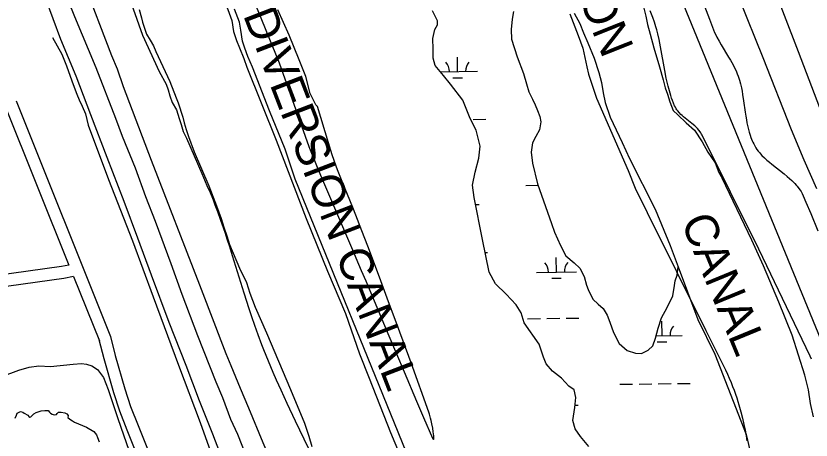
# Model space of a CAD drawing. Extents: x 3715084 to 3753216, y 488173 to 513963.
# Drawn here: x 3731481 to 3733466, y 495879 to 496938 of the extents above; entities that cross this region are included whole.
import ezdxf

# ---------------------------------------------------------------- set-up
doc = ezdxf.new("R2010")
doc.units = 0
for name, color, linetype in [('V-LEVE-TOET', 7, 'Continuous'), ('V-RIVR-IDEN', 7, 'Continuous'), ('V-ROAD-CNTR', 7, 'Continuous'), ('V-SITE-OTLN', 7, 'Continuous'), ('V-SITE-VEGE', 7, 'Continuous'), ('V-TOPO-BNDY', 7, 'Continuous'), ('V-TOPO-SHOR', 7, 'Continuous'), ('V-WETL-SWMP', 7, 'Continuous')]:
    doc.layers.add(name, color=color, linetype=linetype)

msp = doc.modelspace()

# ---------------------------------------------------------------- linework, layer by layer
at = {"layer": 'V-LEVE-TOET'}
for points in [[(3733487.1, 496708.6), (3733434.3, 496848.6), (3733368.3, 497020.1)], [(3731597.9, 497011.3), (3731627.9, 496936.7)], [(3731593.5, 496878.9), (3731555.3, 496983.4)], [(3733286.3, 496981.5), (3733345.1, 496834.6), (3733415.8, 496654.4), (3733447.8, 496578.7), (3733479.4, 496506.9)], [(3731627.9, 496936.7), (3731681.1, 496809.1), (3731730.1, 496682.5), (3731746.7, 496638.2), (3731779.1, 496558.5), (3731804.9, 496487.1), (3731829, 496426.1), (3731868.3, 496319.9), (3731895.6, 496243.2), (3731934.4, 496140.2), (3731980.4, 496025.1), (3731996.7, 495985.4), (3732017.1, 495931.6), (3732034.5, 495893.8), (3732054.2, 495843.7)], [(3731751.6, 496475.2), (3731709.1, 496584.4), (3731668.5, 496691.3), (3731631.8, 496787.7), (3731593.5, 496878.9)], [(3732001, 495819.8), (3731973, 495894.5), (3731939.7, 495977.5), (3731906.1, 496065.7), (3731864.2, 496173), (3731820.2, 496291), (3731785.8, 496383.7), (3731751.6, 496475.2)]]:
    msp.add_lwpolyline(points, dxfattribs=at)
at = {"layer": 'V-ROAD-CNTR'}
for points in [[(3731481.9, 496725.7), (3731717.5, 496138)], [(3731454, 496714.5), (3731613.7, 496316.3)], [(3731613.7, 496316.3), (3731595.5, 496312.3), (3730222.2, 496120.5)], [(3731625, 496288), (3731600.8, 496282.7), (3730229, 496091.2)], [(3731625, 496288), (3731689.7, 496126.8)], [(3731688.6, 496130.7), (3731700.5, 496082.9), (3731724.7, 495998.1), (3731739.6, 495952.8), (3731758.5, 495905.1), (3731822.4, 495744.3), (3731856.9, 495661.6), (3731870.5, 495631.4), (3731886.5, 495592.8), (3731907, 495536), (3731942.4, 495444.7), (3731995.8, 495300.1), (3732029.3, 495210.1), (3732064.1, 495118.1), (3732093.3, 495044.3), (3732122.5, 494975.3), (3732151.9, 494910.5)], [(3731717.7, 496138), (3731729.4, 496090.6), (3731753.3, 496006.9), (3731767.8, 495963.1), (3731786.4, 495916.1), (3731850.2, 495755.6), (3731884.4, 495673.6), (3731898.1, 495643.3), (3731914.4, 495603.6), (3731935.1, 495546.6), (3731970.5, 495455.3), (3732023.9, 495310.5), (3732057.4, 495220.7), (3732092.1, 495128.9), (3732121, 495055.7), (3732150, 494987.4), (3732179.2, 494923), (3732205.9, 494864.4)]]:
    msp.add_lwpolyline(points, dxfattribs=at)
at = {"layer": 'V-SITE-OTLN'}
for p, q in [((3731567.5, 496062.8), (3731624.1, 496069.1)), ((3731624.1, 496069.1), (3731645.2, 496070.7)), ((3731645.2, 496070.7), (3731657.4, 496069.1)), ((3731657.4, 496069.1), (3731671, 496064.7)), ((3731446, 496037.9), (3731488.5, 496054.2)), ((3731488.5, 496054.2), (3731514.2, 496061.1)), ((3731514.2, 496061.1), (3731538.3, 496064.8)), ((3731538.3, 496064.8), (3731567.5, 496062.8)), ((3731671, 496064.7), (3731685.1, 496055.6)), ((3731685.1, 496055.6), (3731700.3, 496035.5)), ((3731700.3, 496035.5), (3731711.9, 496005.3)), ((3731711.9, 496005.3), (3731735.5, 495933.3)), ((3731735.5, 495933.3), (3731778.5, 495809.9))]:
    msp.add_line(p, q, dxfattribs=at)
at = {"layer": 'V-SITE-VEGE'}
for p, q in [((3732069, 496991.8), (3732103.1, 496906.4)), ((3732039.3, 496922.2), (3732027.3, 496955.1)), ((3732163.1, 496889.9), (3732135.4, 496953.2)), ((3732863.5, 496942.8), (3732884.4, 496889)), ((3732043.1, 496902.6), (3732039.3, 496922.2)), ((3732046.8, 496874.8), (3732043.1, 496902.6)), ((3732103.1, 496906.4), (3732138.5, 496821.1)), ((3732188.4, 496828), (3732163.1, 496889.9)), ((3732884.4, 496889), (3732895.8, 496857.4)), ((3732052.5, 496857.1), (3732046.8, 496874.8)), ((3732060.1, 496836.3), (3732052.5, 496857.1)), ((3732895.8, 496857.4), (3732905.8, 496810.7)), ((3732071.5, 496809.7), (3732060.1, 496836.3)), ((3732138.5, 496821.1), (3732212, 496611.9)), ((3732205.2, 496786.9), (3732188.4, 496828)), ((3732114.6, 496700.9), (3732071.5, 496809.7)), ((3732905.8, 496810.7), (3732910.2, 496792.3)), ((3732215.8, 496744), (3732205.2, 496786.9)), ((3732910.2, 496792.3), (3732930.6, 496732.8)), ((3732230.1, 496715.9), (3732215.8, 496744)), ((3732930.6, 496732.8), (3733009.5, 496552)), ((3732233.9, 496711.5), (3732230.1, 496715.9)), ((3732261.6, 496621.6), (3732233.9, 496711.5)), ((3732153.2, 496605.1), (3732114.6, 496700.9)), ((3732166, 496567.6), (3732153.2, 496605.1)), ((3732212, 496611.9), (3732231.3, 496564.7)), ((3732270.8, 496591.6), (3732261.6, 496621.6)), ((3732275.4, 496577.4), (3732270.8, 496591.6)), ((3732178.5, 496530.7), (3732166, 496567.6)), ((3732231.3, 496564.7), (3732245.4, 496530.9)), ((3732280.3, 496563.3), (3732275.4, 496577.4)), ((3732283.8, 496553.9), (3732280.3, 496563.3)), ((3732288.6, 496541.5), (3732283.8, 496553.9)), ((3733009.5, 496552), (3733026.9, 496508.3)), ((3732455, 495850.5), (3732178.5, 496530.7)), ((3732245.4, 496530.9), (3732246.2, 496529.1)), ((3732246.2, 496529.1), (3732318.9, 496359.9)), ((3732295.2, 496525.1), (3732288.6, 496541.5)), ((3732322.5, 496459.5), (3732295.2, 496525.1)), ((3733026.9, 496508.3), (3733056.8, 496447.3)), ((3732330, 496440.7), (3732322.5, 496459.5)), ((3733056.8, 496447.3), (3733203, 496152.8)), ((3732344.9, 496402), (3732330, 496440.7)), ((3732359.7, 496363.2), (3732344.9, 496402)), ((3732318.9, 496359.9), (3732343.4, 496302.9)), ((3732388.9, 496285.6), (3732359.7, 496363.2)), ((3732343.4, 496302.9), (3732354.6, 496276.7)), ((3732408.2, 496233.7), (3732388.9, 496285.6)), ((3732354.6, 496276.7), (3732375.6, 496227.1)), ((3732375.6, 496227.1), (3732412.4, 496139.8)), ((3732433.7, 496164.5), (3732408.2, 496233.7)), ((3732467.5, 496072.2), (3732433.7, 496164.5)), ((3733203, 496152.8), (3733251.8, 496054.6)), ((3732412.4, 496139.8), (3732450.1, 496050)), ((3732512.2, 495949.2), (3732467.5, 496072.2)), ((3732450.1, 496050), (3732481.4, 495976.2)), ((3733251.8, 496054.6), (3733256.9, 496044)), ((3733256.9, 496044), (3733261.6, 496033.6)), ((3733261.6, 496033.6), (3733265.9, 496023.4)), ((3733265.9, 496023.4), (3733269.9, 496013.4)), ((3733269.9, 496013.4), (3733273.5, 496003.7)), ((3733273.5, 496003.7), (3733276.9, 495994.2)), ((3733276.9, 495994.2), (3733280, 495984.9)), ((3732481.4, 495976.2), (3732498.9, 495935.6)), ((3733280, 495984.9), (3733282.8, 495975.9)), ((3733282.8, 495975.9), (3733285.5, 495967.1)), ((3732513.9, 495943.8), (3732512.2, 495949.2)), ((3733285.5, 495967.1), (3733290.2, 495950)), ((3733290.2, 495950), (3733294.3, 495933.8)), ((3732498.9, 495935.6), (3732521.2, 495884.6)), ((3732516.4, 495934.5), (3732513.9, 495943.8)), ((3732517.8, 495928.5), (3732516.4, 495934.5)), ((3732519.5, 495920.1), (3732517.8, 495928.5)), ((3733294.3, 495933.8), (3733297.8, 495918.5)), ((3732521.5, 495908.9), (3732519.5, 495920.1)), ((3732523, 495899.6), (3732521.5, 495908.9)), ((3733297.8, 495918.5), (3733300.8, 495904)), ((3732524.1, 495890.3), (3732523, 495899.6)), ((3732524.3, 495886.1), (3732524.1, 495890.3)), ((3733300.8, 495904), (3733303.4, 495890.4)), ((3733303.4, 495890.4), (3733305.7, 495877.6)), ((3732521.2, 495884.6), (3732522.5, 495882)), ((3732522.5, 495882), (3732523, 495881.4)), ((3732523, 495881.4), (3732523.4, 495881.2)), ((3732523.4, 495881.2), (3732523.7, 495881.2)), ((3732523.7, 495881.2), (3732524, 495881.6)), ((3732524, 495881.6), (3732524.2, 495882.1)), ((3732524.2, 495882.1), (3732524.3, 495883.8)), ((3732524.3, 495883.8), (3732524.3, 495886.1))]:
    msp.add_line(p, q, dxfattribs=at)
for points in [[(3731703.4, 497156.2), (3731797.2, 496889.8), (3731838.8, 496799.1), (3731856.5, 496767.7), (3731861.2, 496753.6), (3731865.5, 496738.2), (3731871.1, 496722.1), (3731882, 496703.3), (3731888.9, 496681.8), (3731893.9, 496667.1), (3731898.9, 496649.7), (3731907, 496633.2), (3731945.5, 496544.6), (3731958.3, 496515), (3731966, 496496.9), (3731973.4, 496478.6), (3731978.2, 496466.4), (3731984.3, 496450), (3731992.3, 496428), (3732002.5, 496398.5), (3732008.1, 496381.6), (3732014.4, 496362.2), (3732021.5, 496340), (3732050.5, 496246.8), (3732062.9, 496208.2), (3732069.7, 496187.6), (3732077.1, 496165.8), (3732085.4, 496142.7), (3732094.5, 496118.1), (3732099.4, 496105.5), (3732111, 496077), (3732122.9, 496048.6), (3732131.1, 496029.8), (3732142.3, 496004.8), (3732157.5, 495971.6), (3732178.3, 495927.5), (3732244.2, 495790.9)], [(3732317.8, 495345.7), (3732291.4, 495411.2), (3732255.8, 495498.3), (3732208.1, 495614.3), (3732181.2, 495679), (3732153.9, 495743.7), (3732098.8, 495872.8), (3732062.4, 495958.9), (3732041.8, 496008.3), (3732018.6, 496064.8), (3732006.5, 496095), (3731993.6, 496127.3), (3731980.2, 496161.9), (3731940.2, 496265.8), (3731820.1, 496577.5), (3731750.2, 496760.6), (3731735.2, 496804.9), (3731721.1, 496838.6), (3731649.9, 497024)], [(3733181.2, 497010.9), (3733211.8, 496929.9), (3733222.2, 496903.1), (3733224.9, 496896.5), (3733227.7, 496890.5), (3733230.4, 496884.9), (3733235.9, 496874.6), (3733241, 496865.7)], [(3733466.3, 496081.3), (3733463.1, 496088.5), (3733335.3, 496355.8), (3733193.9, 496640.5), (3733192.4, 496643.2), (3733190.8, 496645.8), (3733189.2, 496648.3), (3733185.8, 496652.7), (3733182.2, 496656.7), (3733178.7, 496660.3), (3733175.2, 496663.6), (3733168.3, 496669.5), (3733151.2, 496683.2), (3733147.2, 496686.5), (3733143.8, 496689.5), (3733141, 496692.2), (3733136.3, 496697.1), (3733133, 496701), (3733130.8, 496704), (3733129.2, 496706.4), (3733127.1, 496710), (3733125.2, 496713.9), (3733122.5, 496720.4), (3733120, 496726.8), (3733117.7, 496733.1), (3733115.6, 496739.1), (3733112, 496751), (3733108.9, 496762.3), (3733106.3, 496773), (3733104.1, 496783), (3733100.3, 496802), (3733089.9, 496860.5), (3733086.2, 496879.2), (3733083, 496893), (3733080.4, 496903.3), (3733078.3, 496911), (3733074.7, 496922.4), (3733070.8, 496933.7), (3733064.3, 496950.5)], [(3733241, 496865.7), (3733259.7, 496835.1), (3733264.3, 496827.4), (3733270.9, 496815.7), (3733274.1, 496809.8), (3733277, 496803.9), (3733279.5, 496798.5), (3733281.6, 496793.2), (3733283.6, 496788), (3733285.3, 496782.9), (3733286.9, 496778), (3733289.5, 496768.2), (3733291.7, 496758.9), (3733293.4, 496750), (3733294.9, 496741.7), (3733297.3, 496725.9), (3733301.2, 496698.1), (3733302.8, 496687.7), (3733304.3, 496678.7), (3733305.7, 496670.9), (3733307.1, 496664.1), (3733308.5, 496658.2), (3733311.2, 496647.9), (3733313.5, 496640.4), (3733315.4, 496634.8), (3733318.7, 496626.6), (3733320.5, 496622.6), (3733322.4, 496618.6), (3733325, 496613.7), (3733327.7, 496609.1), (3733330.6, 496604.8), (3733333.6, 496600.8), (3733336.7, 496597), (3733339.8, 496593.4), (3733342.9, 496590), (3733349.3, 496583.7), (3733355.6, 496577.9), (3733361.8, 496572.7), (3733367.6, 496567.9), (3733398.8, 496543.6), (3733406.1, 496537.6), (3733412.2, 496532.3), (3733417.4, 496527.5), (3733421.8, 496523.3), (3733425.4, 496519.4), (3733428.5, 496515.9), (3733431.1, 496512.9), (3733435.4, 496507.3), (3733438.4, 496502.9), (3733440.5, 496499.6), (3733443.4, 496494.4), (3733445.9, 496489), (3733452.9, 496472.9), (3733464.8, 496444.6), (3733482.5, 496402)]]:
    msp.add_lwpolyline(points, dxfattribs=at)
at = {"layer": 'V-TOPO-BNDY'}
msp.add_lwpolyline([(3732402.5, 498784.6), (3732445.6, 498679.6), (3734453, 493779.6)], dxfattribs=at)
at = {"layer": 'V-TOPO-SHOR'}
for points in [[(3732001, 496979.4), (3732020, 496926.3), (3732024.4, 496899.2), (3732032, 496876.4), (3732039.5, 496858.1), (3732050.3, 496832.1), (3732057.9, 496810)], [(3733046.3, 496964.2), (3733053.3, 496937), (3733057.7, 496916.8), (3733064, 496892.8), (3733073.5, 496858.7), (3733087.4, 496811.2), (3733096.2, 496778.4), (3733101.9, 496758.1), (3733107.6, 496742.3), (3733113.3, 496723.4), (3733121.5, 496701.9), (3733132.8, 496691.1), (3733154.3, 496671.5), (3733174.6, 496652.5), (3733193.5, 496624.1), (3733208, 496598.2), (3733226.4, 496571.6), (3733235.8, 496547.6), (3733244, 496533.1)], [(3731789.3, 496953.6), (3731795, 496933.4), (3731797.5, 496922), (3731807.6, 496892.3), (3731816.4, 496877.1), (3731824.6, 496863.2), (3731831, 496849.3), (3731836.6, 496836.7)], [(3732874.4, 496944.7), (3732888.9, 496919.4), (3732897.8, 496895.4), (3732908.5, 496870.7), (3732924.3, 496832.8), (3732936.3, 496796.8), (3732942.6, 496772.1), (3732947, 496746.2), (3732952.1, 496721.5), (3732964.1, 496685.5), (3732994.4, 496621.7), (3733012.7, 496581.8)], [(3731573.2, 496884.2), (3731596.5, 496842.2), (3731607.7, 496813.4), (3731616.9, 496787.4), (3731624.5, 496766.7), (3731633.7, 496742.3), (3731639.3, 496728.7), (3731646.6, 496712.9), (3731654.8, 496693.8), (3731661.8, 496665.3)], [(3731836.6, 496836.7), (3731865.9, 496774.2), (3731881.6, 496733.2), (3731886.7, 496721.2), (3731897.9, 496685), (3731901.6, 496670.9), (3731906.6, 496654.9), (3731912.2, 496636.8), (3731926.7, 496598.6), (3731962.8, 496514), (3731982.3, 496463.7), (3731993.6, 496432.8), (3732000.5, 496410.7), (3732008, 496389.3), (3732014.8, 496367.2), (3732039.5, 496308.8), (3732056.7, 496272.5), (3732065.4, 496246.3), (3732078.7, 496210.8), (3732106.6, 496147), (3732166.7, 496006), (3732201.5, 495921.4), (3732212.1, 495889.3), (3732219.5, 495863.8)], [(3732057.9, 496810), (3732131, 496627.9), (3732206, 496432.2), (3732259.3, 496300.6), (3732303.7, 496195.5), (3732338.7, 496094.6), (3732363.1, 496033.9), (3732416.3, 495898.2), (3732437.5, 495846.4), (3732457.7, 495781), (3732491.6, 495720.1), (3732510, 495662.9), (3732538, 495583.2), (3732552.5, 495534.9), (3732570.6, 495495.3), (3732582.8, 495463.2), (3732611, 495393), (3732654.8, 495291.3), (3732700.4, 495176.7), (3732731.7, 495092.1), (3732756.5, 495019.9), (3732785.3, 494944.3), (3732841.8, 494804.4)], [(3731661.8, 496665.3), (3731712.5, 496530.1), (3731772.8, 496376.5), (3731824.1, 496237.1), (3731886.9, 496066), (3731941, 495923.1), (3731987.8, 495793.1), (3732032.8, 495687.2), (3732034.4, 495682.5), (3732033.8, 495677.8), (3732030.2, 495672.6), (3731994.9, 495658.8), (3731904.4, 495628.7)], [(3733012.7, 496581.8), (3733076.3, 496455.4), (3733113.7, 496364.9), (3733133.8, 496311.6)], [(3733471.7, 495937.2), (3733464.3, 495970.5), (3733459.6, 496005.1), (3733450.3, 496041.2), (3733418.6, 496141.3), (3733385.2, 496223.8), (3733346.6, 496313.9), (3733318.2, 496378.7), (3733244, 496533.1)], [(3733133.8, 496311.6), (3733183.4, 496180.1), (3733225.5, 496094), (3733303.7, 495893.5), (3733313, 495854.1)], [(3731480, 495934), (3731482.8, 495941.2), (3731484.8, 495946.2), (3731492.9, 495951), (3731498.5, 495949.4), (3731502.2, 495946.3), (3731511.5, 495941.5), (3731513.9, 495938.6), (3731516.2, 495937), (3731518.9, 495937.6), (3731522.1, 495940.7), (3731526.2, 495945.1), (3731531.7, 495948.2), (3731544.6, 495952), (3731553.6, 495952.9), (3731561.6, 495952.9), (3731565.7, 495949.1), (3731567.8, 495946.8), (3731571.9, 495943.8), (3731577.3, 495942.2), (3731582.6, 495943.5), (3731584.8, 495946.1), (3731588.1, 495949), (3731594.8, 495948.7), (3731603.5, 495947.5), (3731608.6, 495944.7), (3731611.5, 495940.8), (3731611.1, 495936.1), (3731616.3, 495931.6), (3731623.1, 495927.4), (3731627.6, 495924.1), (3731657.6, 495911.9), (3731675.8, 495901.2), (3731682.4, 495892.8), (3731685.5, 495885.5), (3731689.1, 495875.2)]]:
    msp.add_lwpolyline(points, dxfattribs=at)
at = {"layer": 'V-WETL-SWMP'}
for p, q in [((3732583.5, 496799.1), (3732583, 496835.1)), ((3732540.9, 496798.6), (3732633.5, 496799.7)), ((3732571.7, 496783.5), (3732595.7, 496783.8)), ((3732622.1, 496679.5), (3732654.1, 496679.9)), ((3732754.1, 496515), (3732784.5, 496515.4)), ((3732628.8, 496467), (3732637.6, 496467.1)), ((3732652.5, 496347.2), (3732658.3, 496347.3)), ((3732830.2, 496298.7), (3732829.8, 496334.7)), ((3732780.2, 496298), (3732880.2, 496299.3)), ((3732818.4, 496283.1), (3732842.4, 496283.4)), ((3732758.3, 496182.3), (3732790.3, 496182.7)), ((3732806.3, 496182.9), (3732838.3, 496183.3)), ((3732854.3, 496183.5), (3732886.3, 496183.9)), ((3733093.7, 496140.1), (3733093.2, 496176.1)), ((3733079.3, 496139.9), (3733143.7, 496140.7)), ((3733081.9, 496124.5), (3733105.9, 496124.8)), ((3732988.3, 496018.7), (3733020.3, 496019.1)), ((3733036.3, 496019.3), (3733068.3, 496019.7)), ((3733084.3, 496019.9), (3733116.3, 496020.3)), ((3733132.3, 496020.5), (3733164.3, 496020.9)), ((3732876.4, 495966.5), (3732884.4, 495966.6))]:
    msp.add_line(p, q, dxfattribs=at)
for points in [[(3732787, 496119), (3732749.5, 496172), (3732741.9, 496196.6), (3732730.1, 496217.2), (3732704.9, 496243.5), (3732678.3, 496269.2), (3732662, 496298.7), (3732646.1, 496379.7), (3732625.3, 496484.6), (3732621.2, 496515.9), (3732627.3, 496547.7), (3732636.9, 496582.7), (3732639.6, 496613.2), (3732630.3, 496652.7), (3732614.6, 496682.2), (3732596.6, 496727.4), (3732566.3, 496767.4), (3732548.4, 496789.5), (3732527.9, 496814.3), (3732522.9, 496832.8), (3732522.7, 496855.2), (3732521.9, 496881.6), (3732527.1, 496903.9), (3732533.5, 496915.3), (3732533.7, 496926.1), (3732521.4, 496950.8)], [(3732723.4, 496949.2), (3732719.6, 496929.6), (3732717, 496903.9), (3732717.9, 496880.1), (3732731.9, 496835.7), (3732747.9, 496794), (3732755.5, 496768.8), (3732761.2, 496748.3), (3732770.3, 496730.5), (3732777.5, 496716.1), (3732783.2, 496701.7), (3732789, 496687.3), (3732791.5, 496673.7), (3732787.6, 496653.4), (3732778.5, 496637.4), (3732770.7, 496621.2), (3732766.8, 496598.3), (3732770.3, 496570.4), (3732783.4, 496518.5), (3732808.3, 496448.2), (3732817.9, 496420.1), (3732825.6, 496398.3), (3732840.5, 496365.4), (3732853.5, 496339.3), (3732874.1, 496321.9), (3732888.8, 496308.7), (3732899.2, 496287.5), (3732905.5, 496266.3), (3732909.3, 496255.4), (3732921, 496231.4), (3732934.3, 496218.9), (3732947, 496207.8), (3732956.8, 496191.3), (3732963.2, 496173.5), (3732972.8, 496147.5), (3732987.1, 496120.1), (3733006.4, 496102.7), (3733027.3, 496096.2), (3733042.9, 496095.2), (3733059.4, 496103.6), (3733070.5, 496114.9)], [(3733070.5, 496114.9), (3733077.6, 496133.7), (3733084.3, 496158.7), (3733092.3, 496184.3), (3733106.4, 496210.5), (3733120.6, 496239.3), (3733124.5, 496265), (3733126.2, 496277.2), (3733131.2, 496290.6), (3733133.8, 496311.6), (3733183.4, 496180.1), (3733225.5, 496094), (3733303.7, 495893.5), (3733313, 495854.1)], [(3732911.1, 495863.3), (3732890.6, 495888.2), (3732876.8, 495907.4), (3732871.1, 495928.6), (3732875.9, 495961), (3732878.4, 495986.1), (3732874.1, 496004.5), (3732861.4, 496014.3), (3732842.9, 496034.3), (3732820.8, 496051.1), (3732804.3, 496069.8), (3732797.8, 496086.2), (3732787, 496119)]]:
    msp.add_lwpolyline(points, dxfattribs=at)
for centre, start, end in [((3732528.2, 496798.9), 359.9442, 41.4878), ((3732638.7, 496800.3), 139.9442, 181.4878), ((3732775, 496298.4), 359.9442, 41.4878), ((3732885.5, 496299.8), 139.9442, 181.4878), ((3733148.9, 496141.2), 139.9442, 181.4878)]:
    msp.add_arc(centre, 35.2, start, end, dxfattribs=at)

# ---------------------------------------------------------------- texts
at = {"layer": 'V-RIVR-IDEN'}
for s, rotation, p in [('CAERNARVON DIVERSION CANAL', 291.0681, (3731755, 497700.1)), ('CAERNARVON', 291.7408, (3732657.4, 497556.4)), ('CANAL', 292.3801, (3733139.9, 496425.4))]:
    msp.add_text(s, height=83, rotation=rotation, dxfattribs=at).set_placement(p)

doc.saveas('drawing.dxf')
